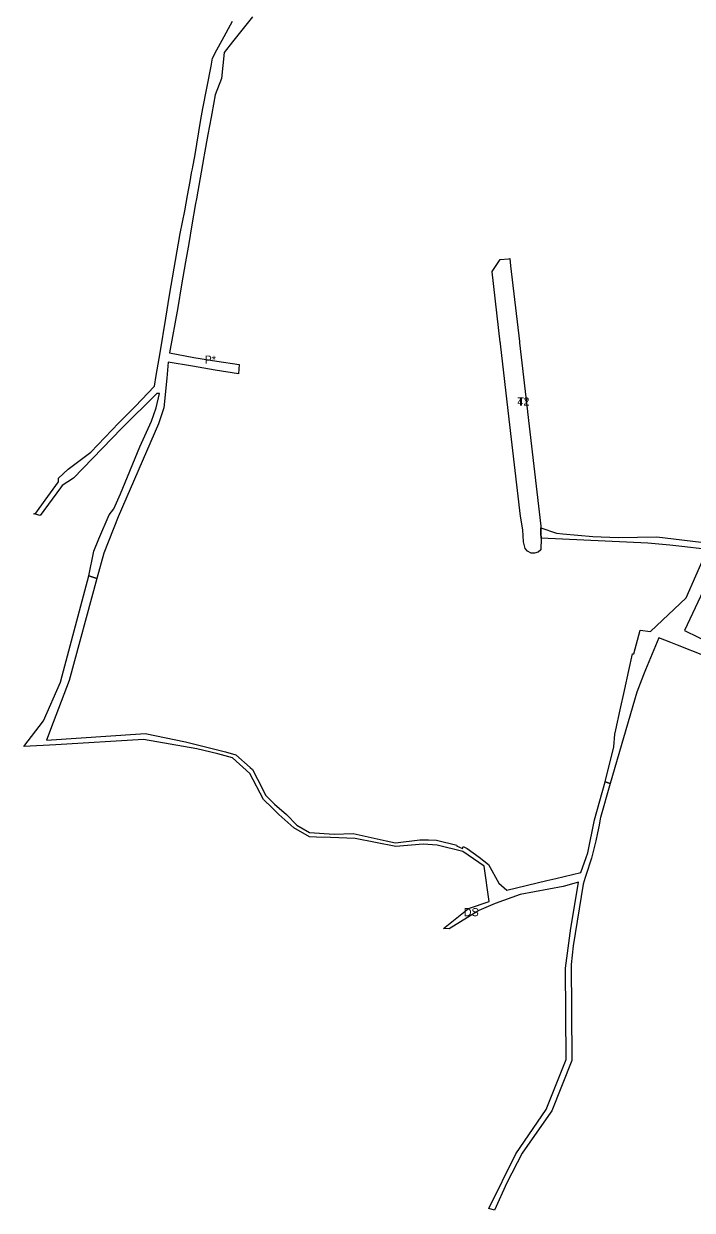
# Model space of a CAD drawing. Extents: x -501732 to -497665, y -1142022 to -1138283.
# Drawn here: x -499400 to -498822, y -1141915 to -1140888 of the extents above; entities that cross this region are included whole.
import ezdxf

# ---------------------------------------------------------------- set-up
doc = ezdxf.new("R2010")
doc.units = 0
for name, color, linetype in [('23', 7, 'Continuous'), ('4', 7, 'Continuous'), ('43', 7, 'Continuous'), ('61', 7, 'Continuous')]:
    doc.layers.add(name, color=color, linetype=linetype)

msp = doc.modelspace()

# ---------------------------------------------------------------- linework, layer by layer
at = {"layer": '23'}
msp.add_lwpolyline([(-498971.151, -1141162.829), (-498971.049, -1141163.707), (-498971.021, -1141163.944), (-498964.157, -1141223.283), (-498964.136, -1141223.466), (-498952.662, -1141322.649), (-498952.505, -1141324.009), (-498952.437, -1141328.802), (-498952.38, -1141332.83), (-498952.45, -1141342.993), (-498955.014, -1141345.143), (-498957.963, -1141346.07), (-498961.047, -1141345.847), (-498964.038, -1141344.347), (-498966.187, -1141341.783), (-498967.437, -1141336.081), (-498968.043, -1141325.881), (-498970.019, -1141313.972), (-498979.825, -1141230.048), (-498979.839, -1141229.927), (-498987.473, -1141164.587), (-498987.577, -1141163.696), (-498987.66, -1141163.7), (-498987.622, -1141163.31), (-498994.728, -1141102.49), (-498994.791, -1141101.957), (-498987.682, -1141091.711), (-498980.599, -1141090.99), (-498979.474, -1141090.876), (-498978.75, -1141097.133)], close=True, dxfattribs=at)
at = {"layer": '4'}
msp.add_lwpolyline([(-499374.68, -1141492.44), (-499380.34, -1141507.82), (-499298.96, -1141502.43), (-499295.03, -1141502.17), (-499259.96, -1141509.41), (-499225.49, -1141517.88), (-499216.44, -1141520.5), (-499204.16, -1141531.39), (-499201.98, -1141533.32), (-499197.76, -1141541.58), (-499190.53, -1141555.72), (-499182.94, -1141563.37), (-499172.75, -1141572.23), (-499163.77, -1141581.45), (-499152.88, -1141587.86), (-499131.4, -1141589.23), (-499115.1, -1141588.54), (-499086.47, -1141594.92), (-499078.38, -1141596.71), (-499057.15, -1141594.05), (-499049.69, -1141594.21), (-499042.9, -1141594.35), (-499025.32, -1141598.87), (-499025.57, -1141599.47), (-499020.41, -1141601.64), (-499019.7, -1141599.96), (-499016.32, -1141601.63), (-499006, -1141609.03), (-498997.73, -1141615.43), (-498988.93, -1141631.68), (-498981.99, -1141637.66), (-498947.46, -1141629.37), (-498939.49, -1141627.48), (-498918.04, -1141622.38), (-498913.2, -1141609.38), (-498911.81, -1141605.52), (-498906.01, -1141576.76), (-498896.76, -1141543.88), (-498892.491, -1141545.478), (-498900.97, -1141574.67), (-498901.19, -1141575.92), (-498902.14, -1141581.32), (-498903.64, -1141587.99), (-498904.82, -1141594.87), (-498908.71, -1141609.93), (-498913.62, -1141624.92), (-498914.2, -1141626.85), (-498915.81, -1141632.6), (-498924.6, -1141685.96), (-498926.39, -1141702.15), (-498926.05, -1141741.69), (-498925.67, -1141785.22), (-498943.06, -1141828.91), (-498945.8, -1141832.8), (-498968.75, -1141865.46), (-498981.9, -1141891.14), (-498992.79, -1141914.86), (-498997.66, -1141913.35), (-498974.11, -1141865.96), (-498947.98, -1141827.73), (-498930.78, -1141784.47), (-498931.31, -1141705.25), (-498926.5, -1141670.63), (-498920.59, -1141634.58), (-498919.95, -1141630.71), (-498933.25, -1141634.59), (-498970.42, -1141641.59), (-498991.95, -1141649.27), (-499006.17, -1141655.31), (-499031.84, -1141671.1), (-499036.81, -1141671.03), (-499015.11, -1141653.67), (-498997.4, -1141647.48), (-499001.68, -1141617), (-499019.94, -1141604.31), (-499042.32, -1141598.82), (-499054.3, -1141597.84), (-499078.04, -1141599.95), (-499113.37, -1141592.87), (-499134.62, -1141592.19), (-499146.64, -1141591.81), (-499152.68, -1141591.62), (-499166.23, -1141583.87), (-499179.32, -1141572.09), (-499185.07, -1141566.51), (-499192.44, -1141559.35), (-499204.5, -1141536.85), (-499219.48, -1141523.27), (-499232, -1141519.68), (-499250.27, -1141515.5), (-499296.43, -1141507.22), (-499372.26, -1141511.76), (-499400.064, -1141513.467), (-499383.03, -1141491.07), (-499368.18, -1141457.7), (-499366.75, -1141452.15), (-499343.75, -1141365.68), (-499336.814, -1141367.918), (-499360.85, -1141456.27)], close=True, dxfattribs=at)
at = {"layer": '43'}
for points in [[(-499202.02, -1140881.64), (-499219.29, -1140903.33), (-499226.63, -1140912.54), (-499229.06, -1140935.09), (-499234.39, -1140949.05), (-499237.4, -1140965.44), (-499237.96, -1140968.39), (-499240.81, -1140983.63), (-499243.84, -1141001.08), (-499244.15, -1141002.76), (-499246.444, -1141016.002), (-499247.31, -1141021), (-499250.48, -1141039.11), (-499251.28, -1141043.23), (-499254.61, -1141061.82), (-499257.32, -1141077.91), (-499260, -1141093.68), (-499263.4, -1141113.64), (-499266.76, -1141133.36), (-499273.81, -1141172.52), (-499252.78, -1141176.42), (-499233.1, -1141179.6), (-499213.77, -1141182.72), (-499214.24, -1141190.66), (-499234.29, -1141187.5), (-499253.99, -1141184.19), (-499275, -1141180.67), (-499276.33, -1141194.46), (-499278.81, -1141219.99), (-499283.43, -1141234.07), (-499318.37, -1141314.58), (-499330.87, -1141346.07), (-499336.814, -1141367.918), (-499343.75, -1141365.68), (-499339.45, -1141344.12), (-499334.99, -1141333.68), (-499326.26, -1141312.71), (-499322.11, -1141307.71), (-499316.27, -1141294.64), (-499299.5, -1141254.03), (-499289.45, -1141231.55), (-499285.32, -1141220.1), (-499282.62, -1141207.83), (-499284.9, -1141207.63), (-499315.36, -1141237.96), (-499356.92, -1141281), (-499366.91, -1141287.35), (-499368.37, -1141289.28), (-499385.94, -1141313.48), (-499391.211, -1141311.789), (-499389.6, -1141311.34), (-499381.42, -1141299.95), (-499370.06, -1141284.15), (-499370.01, -1141281.01), (-499361.58, -1141273.32), (-499341.88, -1141258.59), (-499317.74, -1141233.15), (-499310.97, -1141226.31), (-499303.74, -1141219.01), (-499286.84, -1141201.25), (-499285.32, -1141192.18), (-499282.02, -1141172.45), (-499276.99, -1141142.38), (-499273.96, -1141122.71), (-499264.78, -1141069.13), (-499260.74, -1141049.54), (-499258.3, -1141036.16), (-499256.1, -1141024.05), (-499254.75, -1141016.63), (-499254.152, -1141013.317), (-499253.8, -1141011.37), (-499252.11, -1141002.41), (-499246.75, -1140970.51), (-499245.16, -1140961.04), (-499237.88, -1140924.28), (-499236.82, -1140917.34), (-499232.84, -1140910.06), (-499228.39, -1140901.93), (-499219.31, -1140885.35)], [(-498749.42, -1141245.53), (-498828.34, -1141412.8), (-498769.13, -1141441.85)], [(-498810.61, -1141342.44), (-498830.66, -1141340.16), (-498841, -1141339.1), (-498859.93, -1141337.21), (-498952.38, -1141332.83), (-498952.437, -1141328.802), (-498952.505, -1141324.009), (-498939, -1141328.7), (-498933.47, -1141329.23), (-498907.56, -1141331.44), (-498885.51, -1141332.5), (-498852.29, -1141331.91), (-498806.51, -1141337.22)], [(-498787.53, -1141444.07), (-498834.17, -1141425.47), (-498839.96, -1141423.17), (-498850.3, -1141419.16), (-498861.93, -1141446.88), (-498863.67, -1141451.35), (-498869.5, -1141466.33), (-498892.491, -1141545.478), (-498896.76, -1141543.88), (-498889.34, -1141513.58), (-498888.59, -1141502.67), (-498887.77, -1141498.98), (-498883.92, -1141481.68), (-498880.08, -1141464.76), (-498876.29, -1141447.41), (-498873.1, -1141433.06), (-498872.01, -1141433.24), (-498866.63, -1141412.51), (-498857.77, -1141413.82), (-498826.65, -1141384.51), (-498809.989, -1141346.416)]]:
    msp.add_lwpolyline(points, dxfattribs=at)

# ---------------------------------------------------------------- texts
at = {"layer": '23'}
msp.add_text('T*', height=7, dxfattribs=at).set_placement((-498972.882, -1141218.14))
at = {"layer": '4'}
msp.add_text('DS', height=7, dxfattribs=at).set_placement((-499019.301, -1141660.259))
at = {"layer": '43'}
msp.add_text('P*', height=7, dxfattribs=at).set_placement((-499243.528, -1141181.914))
at = {"layer": '61'}
msp.add_text('42', height=7, dxfattribs=at).set_placement((-498972.874, -1141218.14))

doc.saveas('drawing.dxf')
